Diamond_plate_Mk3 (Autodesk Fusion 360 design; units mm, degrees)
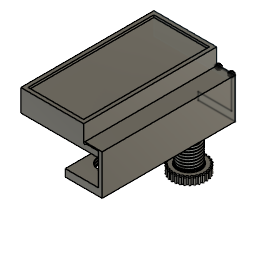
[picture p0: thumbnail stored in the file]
sketch "Sketch1" plane through (0, 0, 0) normal (0, 0, 1) x axis (1, 0, 0)
  line L1 (95.1956, 180.5) -> (20.1956, 180.5)
  line L2 (95.1956, 10.5) -> (95.1956, 180.5)
  line L3 (20.1956, 10.5) -> (95.1956, 10.5)
  line L4 (20.1956, 180.5) -> (20.1956, 10.5)
  line L5 (100.1956, 185.5) -> (15.1956, 185.5)
  line L6 (100.1956, 5.5) -> (100.1956, 185.5)
  line L7 (15.1956, 5.5) -> (100.1956, 5.5)
  line L8 (15.1956, 185.5) -> (15.1956, 5.5)
  point P2 (20.1956, 180.5)
  point P3 (95.1956, 180.5)
  point P4 (95.1956, 10.5)
  horizontal L1
  vertical L2
  horizontal L3
  vertical L4
  horizontal L5
  vertical L6
  horizontal L7
  vertical L8
  dimension "d1" distance P2 P3 = 75
  dimension "d2" distance P3 P4 = 170
  dimension "d3" distance L2 L6 = 5
  dimension "d4" distance L1 L5 = 5
  dimension "d5" distance L4 L8 = 5
  dimension "d6" distance L3 L7 = 5
extrude "Extrude1" new body sketch "Sketch1" against normal blind 30
extrude "Extrude2" cut sketch "Sketch1" profile of L1 L2 L3 L4 against normal blind 3
sketch "Sketch2" plane through (0, 0, -30) normal (0, 0, -1) x axis (1, 0, 0)
  line L1 (15.1956, -5.5) -> (100.1956, -5.5)
  line L2 (15.1956, -185.5) -> (15.1956, -5.5)
  line L3 (100.1956, -185.5) -> (15.1956, -185.5)
  line L4 (100.1956, -5.5) -> (100.1956, -185.5)
  line L5 (120.1956, -5.5) -> (44.4029, -5.5)
  line L6 (120.1956, -185.5) -> (120.1956, -5.5)
  line L7 (44.4029, -185.5) -> (120.1956, -185.5)
  line L8 (44.4029, -5.5) -> (44.4029, -185.5)
  point P6 (44.4029, -5.5)
  point P9 (44.4029, -185.5)
  horizontal L5
  vertical L6
  horizontal L7
  vertical L8
  coincident L1 P6
  coincident L3 P9
  dimension "d11" distance L4 L6 = 20
extrude "Extrude3" add sketch "Sketch2" profile of L4 L5 L6 L7 against normal blind 8
sketch "Sketch3" plane through (0, 185.5, 0) normal (0, 1, 0) x axis (-1, 0, 0)
  line L1 (-100.1956, 0) -> (-15.1956, 0)
  line L2 (-100.1956, -22) -> (-100.1956, 0)
  line L3 (-120.1956, -22) -> (-100.1956, -22)
  line L4 (-120.1956, -30) -> (-120.1956, -22)
  line L5 (-15.1956, -30) -> (-120.1956, -30)
  line L6 (-15.1956, 0) -> (-15.1956, -30)
  line L7 (-102.948, -20.5) -> (-101.6956, -20.5)
  line L8 (-125.1956, -20.5) -> (-102.948, -20.5)
  line L9 (-125.1956, -75) -> (-75.1956, -75)
  line L10 (-125.1956, -20.5) -> (-125.1956, -75)
  line L11 (-120.1956, -22) -> (-103.1956, -22)
  line L12 (-120.1956, -65) -> (-120.1956, -22)
  line L13 (-75.1956, -65) -> (-120.1956, -65)
  line L14 (-75.1956, -75) -> (-75.1956, -65)
  circle C1 centre (-101.6956, -22) radius 1.5
  point P8 (-101.6956, -22)
  point P9 (-101.6956, -20.5)
  point P14 (-103.1956, -22)
  point P5 (-120.1956, -22)
  point P15 (-120.1956, -22)
  point P16 (-120.1956, -22)
  point P17 (-120.1956, -65)
  coincident L3 P8
  tangent L2 C1
  coincident C1 P9
  tangent C1 L7
  perpendicular L2 L7
  perpendicular L2 L8
  horizontal L9
  vertical L10
  coincident C1 P14
  coincident L3 P14
  coincident P5 P15
  coincident P5 P16
  perpendicular L11 L12
  perpendicular L12 L13
  vertical L14
  dimension "d14" diameter C1 = 3
  dimension "d17" distance L5 P17 = 35
  dimension "d18" distance L10 L12 = 5
  dimension "d40" distance L9 L13 = 10
  dimension "d41" distance L10 L14 = 50
extrude "Extrude4" cut sketch "Sketch3" profile of L3 C1 against normal blind 264
extrude "Extrude5" new body sketch "Sketch3" profile of L3 L4 C1 L7 L8 L9 L10 L11 L12 L13 L14 to an object
sketch "Sketch4" plane through (0, 0, -75) normal (0, 0, -1) x axis (1, 0, 0)
  line L1 (75.1956, -5.5) -> (125.1956, -5.5)
  line L2 (75.1956, -185.5) -> (75.1956, -5.5)
  line L3 (125.1956, -185.5) -> (75.1956, -185.5)
  line L4 (125.1956, -5.5) -> (125.1956, -185.5)
  line L5 (75.1956, -185.5) -> (120.1956, -185.5)
  line L6 (97.6956, -5.5) -> (97.6956, -185.5)
  circle C1 centre (97.6956, -150.5) radius 15
  circle C2 centre (97.6956, -40.5) radius 15
  point P10 (97.6956, -185.5)
  point P11 (97.6956, -5.5)
  point P6 (97.6956, -150.5)
  point P7 (97.6956, -40.5)
  equal C1 C2
  midpoint L5 P10
  coincident L1 P11
  perpendicular L1 L6
  coincident P6 L6
  coincident P7 L6
  dimension "d21" diameter C1 = 30
  dimension "d22" distance L3 P6 = 35
  dimension "d23" distance L1 P7 = 35
extrude "Extrude6" cut sketch "Sketch4" profile of C1 C2 to an object
extrude "Extrude7" new body sketch "Sketch4" profile of C1 along normal blind 40
thread "Thread1" ThreadOffset 0 ThreadLength 10
thread "Thread2" ThreadOffset 0 ThreadLength 10
sketch "Sketch5" plane through (0, 0, -115) normal (0, 0, -1) x axis (1, 0, 0)
  line L1 (75.1956, -5.5) -> (75.1956, -185.5)
  line L2 (97.6956, -150.5) -> (83.9094, -168.2818)
  line L3 (80.5137, -165.0269) -> (97.6956, -150.5)
  circle C1 centre (97.6956, -150.5) radius 15
  circle C2 centre (97.6956, -150.5) radius 22.5
  arc A1 centre (90.1929, -129.0088) radius 1.2018 clockwise from (91.3899, -128.9017) to (89.1893, -129.6699)
  arc A2 centre (92.5869, -128.7946) radius 1.2018 clockwise from (91.3899, -128.9017) to (93.706, -128.3566)
  arc A3 centre (85.8886, -131.0383) radius 1.2018 clockwise from (87.0372, -130.6847) to (85.0444, -131.8937)
  arc A4 centre (88.1857, -130.3311) radius 1.2018 clockwise from (87.0372, -130.6847) to (89.1893, -129.6699)
  arc A5 centre (82.1003, -133.9184) radius 1.2018 clockwise from (83.1502, -133.3337) to (81.4524, -134.9306)
  arc A6 centre (84.2002, -132.7491) radius 1.2018 clockwise from (83.1502, -133.3337) to (85.0444, -131.8937)
  arc A7 centre (78.9936, -137.5232) radius 1.2018 clockwise from (79.899, -136.733) to (78.5703, -138.648)
  arc A8 centre (80.8045, -135.9428) radius 1.2018 clockwise from (79.899, -136.733) to (81.4524, -134.9306)
  arc A9 centre (76.7042, -141.6952) radius 1.2018 clockwise from (77.4256, -140.734) to (76.524, -142.8834)
  arc A10 centre (78.147, -139.7728) radius 1.2018 clockwise from (77.4256, -140.734) to (78.5703, -138.648)
  arc A11 centre (75.3323, -146.252) radius 1.2018 clockwise from (75.8381, -145.1618) to (75.4031, -147.4517)
  arc A12 centre (76.3438, -144.0716) radius 1.2018 clockwise from (75.8381, -145.1618) to (76.524, -142.8834)
  arc A13 centre (74.9378, -150.9944) radius 1.2018 clockwise from (75.2058, -149.8229) to (75.2565, -152.1532)
  arc A14 centre (75.4739, -148.6514) radius 1.2018 clockwise from (75.2058, -149.8229) to (75.4031, -147.4517)
  arc A15 centre (75.5379, -155.7152) radius 1.2018 clockwise from (75.5565, -154.5136) to (76.0905, -156.7824)
  arc A16 centre (75.5751, -153.3119) radius 1.2018 clockwise from (75.5565, -154.5136) to (75.2565, -152.1532)
  arc A17 centre (77.1064, -160.2081) radius 1.2018 clockwise from (76.8748, -159.0289) to (77.8688, -161.1371)
  arc A18 centre (76.6431, -157.8496) radius 1.2018 clockwise from (76.8748, -159.0289) to (76.0905, -156.7824)
  arc A19 centre (79.5747, -164.2767) radius 1.2018 clockwise from (79.103, -163.1714) to (80.5137, -165.0269)
  arc A20 centre (78.6313, -162.0661) radius 1.2018 clockwise from (79.103, -163.1714) to (77.8688, -161.1371)
  arc A21 centre (82.8351, -167.7432) radius 1.2018 clockwise from (82.1438, -166.7601) to (83.9094, -168.2818)
  arc A22 centre (81.4526, -165.777) radius 1.2018 clockwise from (82.1438, -166.7601) to (80.5137, -165.0269)
  arc A23 centre (86.7449, -170.4561) radius 1.2018 clockwise from (85.8643, -169.6382) to (87.9077, -170.7595)
  arc A24 centre (84.9838, -168.8203) radius 1.2018 clockwise from (85.8643, -169.6382) to (83.9094, -168.2818)
  arc A25 centre (91.1333, -172.2968) radius 1.2018 clockwise from (90.1019, -171.6799) to (92.3338, -172.3518)
  arc A26 centre (89.0706, -171.0629) radius 1.2018 clockwise from (90.1019, -171.6799) to (87.9077, -170.7595)
  arc A27 centre (95.8085, -173.1849) radius 1.2018 clockwise from (94.6714, -172.7959) to (96.9942, -172.9891)
  arc A28 centre (93.5343, -172.4068) radius 1.2018 clockwise from (94.6714, -172.7959) to (92.3338, -172.3518)
  arc A29 centre (100.5662, -173.0815) radius 1.2018 clockwise from (99.373, -172.9374) to (101.6853, -172.6435)
  arc A30 centre (98.1799, -172.7933) radius 1.2018 clockwise from (99.373, -172.9374) to (96.9942, -172.9891)
  arc A31 centre (105.1984, -171.9913) radius 1.2018 clockwise from (104.0014, -172.0984) to (106.202, -171.3301)
  arc A32 centre (102.8044, -172.2054) radius 1.2018 clockwise from (104.0014, -172.0984) to (101.6853, -172.6435)
  arc A33 centre (109.5027, -169.9617) radius 1.2018 clockwise from (108.3541, -170.3153) to (110.3469, -169.1064)
  arc A34 centre (107.2055, -170.669) radius 1.2018 clockwise from (108.3541, -170.3153) to (106.202, -171.3301)
  arc A35 centre (113.291, -167.0816) radius 1.2018 clockwise from (112.2411, -167.6663) to (113.9389, -166.0694)
  arc A36 centre (111.1911, -168.251) radius 1.2018 clockwise from (112.2411, -167.6663) to (110.3469, -169.1064)
  arc A37 centre (116.3977, -163.4768) radius 1.2018 clockwise from (115.4923, -164.267) to (116.821, -162.352)
  arc A38 centre (114.5868, -165.0572) radius 1.2018 clockwise from (115.4923, -164.267) to (113.9389, -166.0694)
  arc A39 centre (118.6871, -159.3048) radius 1.2018 clockwise from (117.9657, -160.2661) to (118.8673, -158.1166)
  arc A40 centre (117.2443, -161.2273) radius 1.2018 clockwise from (117.9657, -160.2661) to (116.821, -162.352)
  arc A41 centre (120.059, -154.7481) radius 1.2018 clockwise from (119.5532, -155.8383) to (119.9882, -153.5484)
  arc A42 centre (119.0474, -156.9284) radius 1.2018 clockwise from (119.5532, -155.8383) to (118.8673, -158.1166)
  arc A43 centre (120.4535, -150.0057) radius 1.2018 clockwise from (120.1855, -151.1772) to (120.1348, -148.8469)
  arc A44 centre (119.9174, -152.3487) radius 1.2018 clockwise from (120.1855, -151.1772) to (119.9882, -153.5484)
  arc A45 centre (119.8534, -145.2848) radius 1.2018 clockwise from (119.8348, -146.4865) to (119.3008, -144.2176)
  arc A46 centre (119.8162, -147.6881) radius 1.2018 clockwise from (119.8348, -146.4865) to (120.1348, -148.8469)
  arc A47 centre (118.2849, -140.7919) radius 1.2018 clockwise from (118.5165, -141.9712) to (117.5225, -139.863)
  arc A48 centre (118.7481, -143.1505) radius 1.2018 clockwise from (118.5165, -141.9712) to (119.3008, -144.2176)
  arc A49 centre (115.8166, -136.7233) radius 1.2018 clockwise from (116.2883, -137.8287) to (114.8776, -135.9732)
  arc A50 centre (116.76, -138.934) radius 1.2018 clockwise from (116.2883, -137.8287) to (117.5225, -139.863)
  arc A51 centre (112.5562, -133.2568) radius 1.2018 clockwise from (113.2475, -134.2399) to (111.4819, -132.7183)
  arc A52 centre (113.9387, -135.223) radius 1.2018 clockwise from (113.2475, -134.2399) to (114.8776, -135.9732)
  arc A53 centre (108.6464, -130.544) radius 1.2018 clockwise from (109.527, -131.3618) to (107.4836, -130.2405)
  arc A54 centre (110.4075, -132.1797) radius 1.2018 clockwise from (109.527, -131.3618) to (111.4819, -132.7183)
  arc A55 centre (104.258, -128.7032) radius 1.2018 clockwise from (105.2894, -129.3202) to (103.0575, -128.6482)
  arc A56 centre (106.3207, -129.9371) radius 1.2018 clockwise from (105.2894, -129.3202) to (107.4836, -130.2405)
  arc A57 centre (99.5828, -127.8152) radius 1.2018 clockwise from (100.7199, -128.2042) to (98.3971, -128.011)
  arc A58 centre (101.857, -128.5932) radius 1.2018 clockwise from (100.7199, -128.2042) to (103.0575, -128.6482)
  arc A59 centre (94.8251, -127.9185) radius 1.2018 clockwise from (96.0183, -128.0626) to (93.706, -128.3566)
  arc A60 centre (97.2114, -128.2068) radius 1.2018 clockwise from (96.0183, -128.0626) to (98.3971, -128.011)
  point P7 (91.3899, -128.9017)
  point P6 (89.1893, -129.6699)
  point P9 (93.706, -128.3566)
  point P3 (97.6956, -150.5)
  point P106 (97.6956, -150.5)
  concentric C1 C2
  tangent C2 L1
  coincident C2 P7
  coincident C2 P6
  tangent A1 A2
  coincident C2 P9
  equal A1 A2
  coincident P3 P106
  dimension "d44" angle L2 L3 = 12 (= "( 360 / 30 ) * 1 deg")
  dimension "d33" C-Pattern1-Angle = 360
extrude "Extrude8" add sketch "Sketch5" profile of C1 C2 L1 A1 A2 A3 A4 A5 A6 A7 A8 A9 A10 A11 A12 A13 A14 A15 A16 A17 A18 A19 A20 A21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 against normal blind 10
fillet "Fillet2" radius 1
thread "Thread3" ThreadOffset 0 ThreadLength 10
move "Move1"
fillet "Fillet3" radius 1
